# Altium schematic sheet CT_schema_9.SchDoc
size 226 x 144 mm
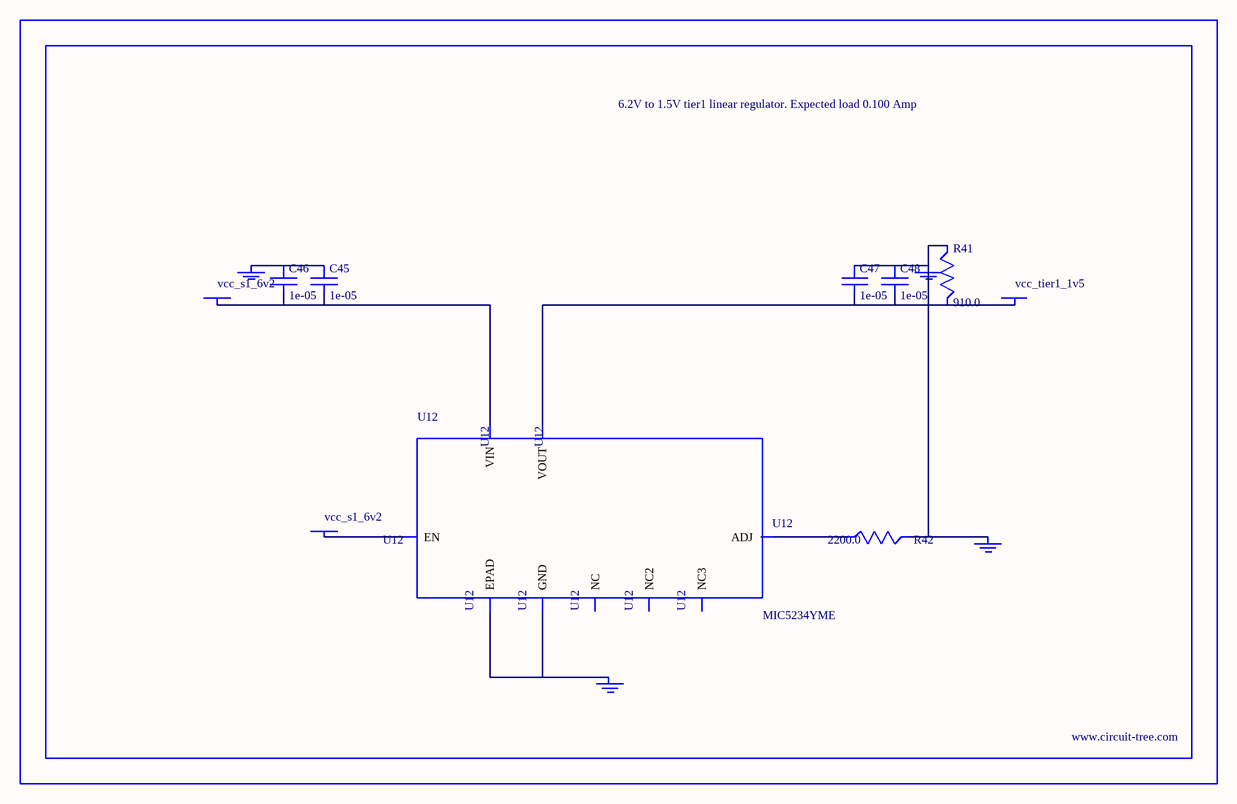
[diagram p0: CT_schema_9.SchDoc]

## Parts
BORDER8  (no value)
C45  1e-05  [C1210]
C46  1e-05  [C1210]
C47  1e-05  [C1210]
C48  1e-05  [C1210]
GND_INSTANCE_8_0  (no value)
GND_INSTANCE_8_1  (no value)
GND_INSTANCE_8_2  (no value)
GND_INSTANCE_8_3  (no value)
POWER_INSTANCE_8_0  vcc_tier1_1v5
POWER_INSTANCE_8_1  vcc_s1_6v2
POWER_INSTANCE_8_2  vcc_s1_6v2
R41  910.0  [R0603]
R42  2200.0  [R0603]
U12  MIC5234YME  [SOIC-8_EP]

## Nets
NetC45_1: C45.1 C46.1 GND_INSTANCE_8_3.0(GND)
NetC45_2: C45.2 C46.2 POWER_INSTANCE_8_2.0(PWR) U12.8(VIN)
NetC47_1: C47.1 C48.1 GND_INSTANCE_8_0.0(GND) GND_INSTANCE_8_1.0(GND) R41.1 R42.2
NetC47_2: C47.2 C48.2 POWER_INSTANCE_8_0.0(PWR) R41.2 U12.1(VOUT)
NetGND_INSTANCE_8_2_0: GND_INSTANCE_8_2.0(GND) U12.7(GND) U12.EPAD
NetPOWER_INSTANCE_8_1_0: POWER_INSTANCE_8_1.0(PWR) U12.5(EN)
NetR42_1: R42.1 U12.4(ADJ)

Not connected (* = marked no-connect by the designer): U12 2(NC) 3(NC2) 6(NC3)

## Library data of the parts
BORDER8 = BORDER_PAGE8
C45-C48 = C1210C106K5PACTU
GND_INSTANCE_8_0-GND_INSTANCE_8_3 = GND
POWER_INSTANCE_8_0-POWER_INSTANCE_8_2 = PWR
R41 = RC0603JR-07910RL
R42 = RC0603JR-072K2L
